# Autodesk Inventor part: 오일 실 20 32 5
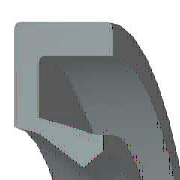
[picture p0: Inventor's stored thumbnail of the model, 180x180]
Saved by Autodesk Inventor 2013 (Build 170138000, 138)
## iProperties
IsCustomPart: 0
Created: 2012-02
Part Number: 오일 실 20 32 5
Material: 고무
Description: 오일 실 - 비스프링, 조립 GA
Document SubType Name: Modeling
Standard: JIS B 2402
Designer: mduedu
Standards Organization: JIS
Language: ko-KR
Size Designation: 20 32 5 A
Categories: <MemberInstance><Categories><Category DisplayName="샤프트 부품" InternalName="7f7aeb1f-a693-4053-b835-cee3144e0d98" Mnemonic="SHFT"><Category DisplayName="실링" Intern
Density: 0.93 g/cm^3
Author: mduedu
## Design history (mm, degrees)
fillet "모깎기2" dims "d33" = 0.5
body "Solid1"
revolve "회전1" stored, may be unused: angle "d27" = 360 deg
fillet "모깎기1" dims "d28" = 0.25 (= 0.05 x b)
sketch "스케치2"
  geometry: L1 (11.971, -3.75)-(12.571, -5); L2 (11.171, -3.438)-(11.971, -3.75); L3 (10, -1.375)-(11.171, -3.438); L4 (10.923, -0.75)-(10, -1.375); L5 (13.6, -4.375)-(10.923, -0.75); L6 (13.6, -0.25)-(13.6, -4.375); L7 (14.8, -0.25)-(13.6, -0.25); L8 (14.8, 0)-(14.8, -0.25); L9 (16, 0)-(14.8, 0); L10 (16, -5)-(16, 0); L11 (12.571, -5)-(16, -5); L12 (0, -9.6)-(0, 1.6) reference; L13 (28, 0)-(14, 0) reference
  constraints: 22 end point, 3 horizontal, 3 vertical
  dimensions: "d2" = 5 distance of L10.start L9.start (= b); "d4" = 1.2 distance of L9.start L8.start (= 0.1 x dd - 0.1 x Diam); "d6" = 0.25 distance of L8.start L7.start (= 0.05 x b); "d8" = 0.92308 horizontal distance of L4.start L3.start (= 0.0769231 x dd - 0.0769231 x Diam); "d10" = 0.625 vertical distance of L5.start L10.start (= 0.125 x b); "d12" = 1.2 distance of L7.start L6.start (= 0.1 x dd - 0.1 x Diam); "d14" = 0.5 vertical distance of L4.start L6.start (= 0.1 x b); "d16" = 3.42857 distance of L1.end L10.start (= 0.285714 x dd - 0.285714 x Diam); "d18" = 0.6 horizontal distance of L1.start L1.end (= 0.05 x dd - 0.05 x Diam); "d20" = 0.625 vertical distance of L4.start L3.start (= 0.125 x b); "d22" = 1.25 vertical distance of L1.start L1.end (= 0.25 x b); "d24" = 0.8 horizontal distance of L2.start L1.start (= 0.0666667 x dd - 0.0666667 x Diam); "d26" = 0.3125 vertical distance of L2.start L1.start (= 0.0625 x b); "d29" = 0 distance between parallel lines of L13 L9; "d30" = 10 distance from line of L3.start L12 (= 0.5 x Diam); "d31" = 16 distance between parallel lines of L12 L10 (= 0.5 x dd)
other parameters: "dd" = 32 [user parameter; used in 7 equation terms], "b" = 5 [user parameter; used in 8 equation terms], "d1" = 8 (derived), "d3" = 2 (derived), "d5" = 0.4 (derived), "d7" = 1.53846 (derived), "d9" = 1 (derived), "d11" = 2 (derived), "d13" = 0.8 (derived), "d15" = 5.71429 (derived), "d17" = 1 (derived), "d19" = 1 (derived), "d21" = 2 (derived), "d23" = 1.33333 (derived), "d25" = 0.5 (derived), "d32" = 0
